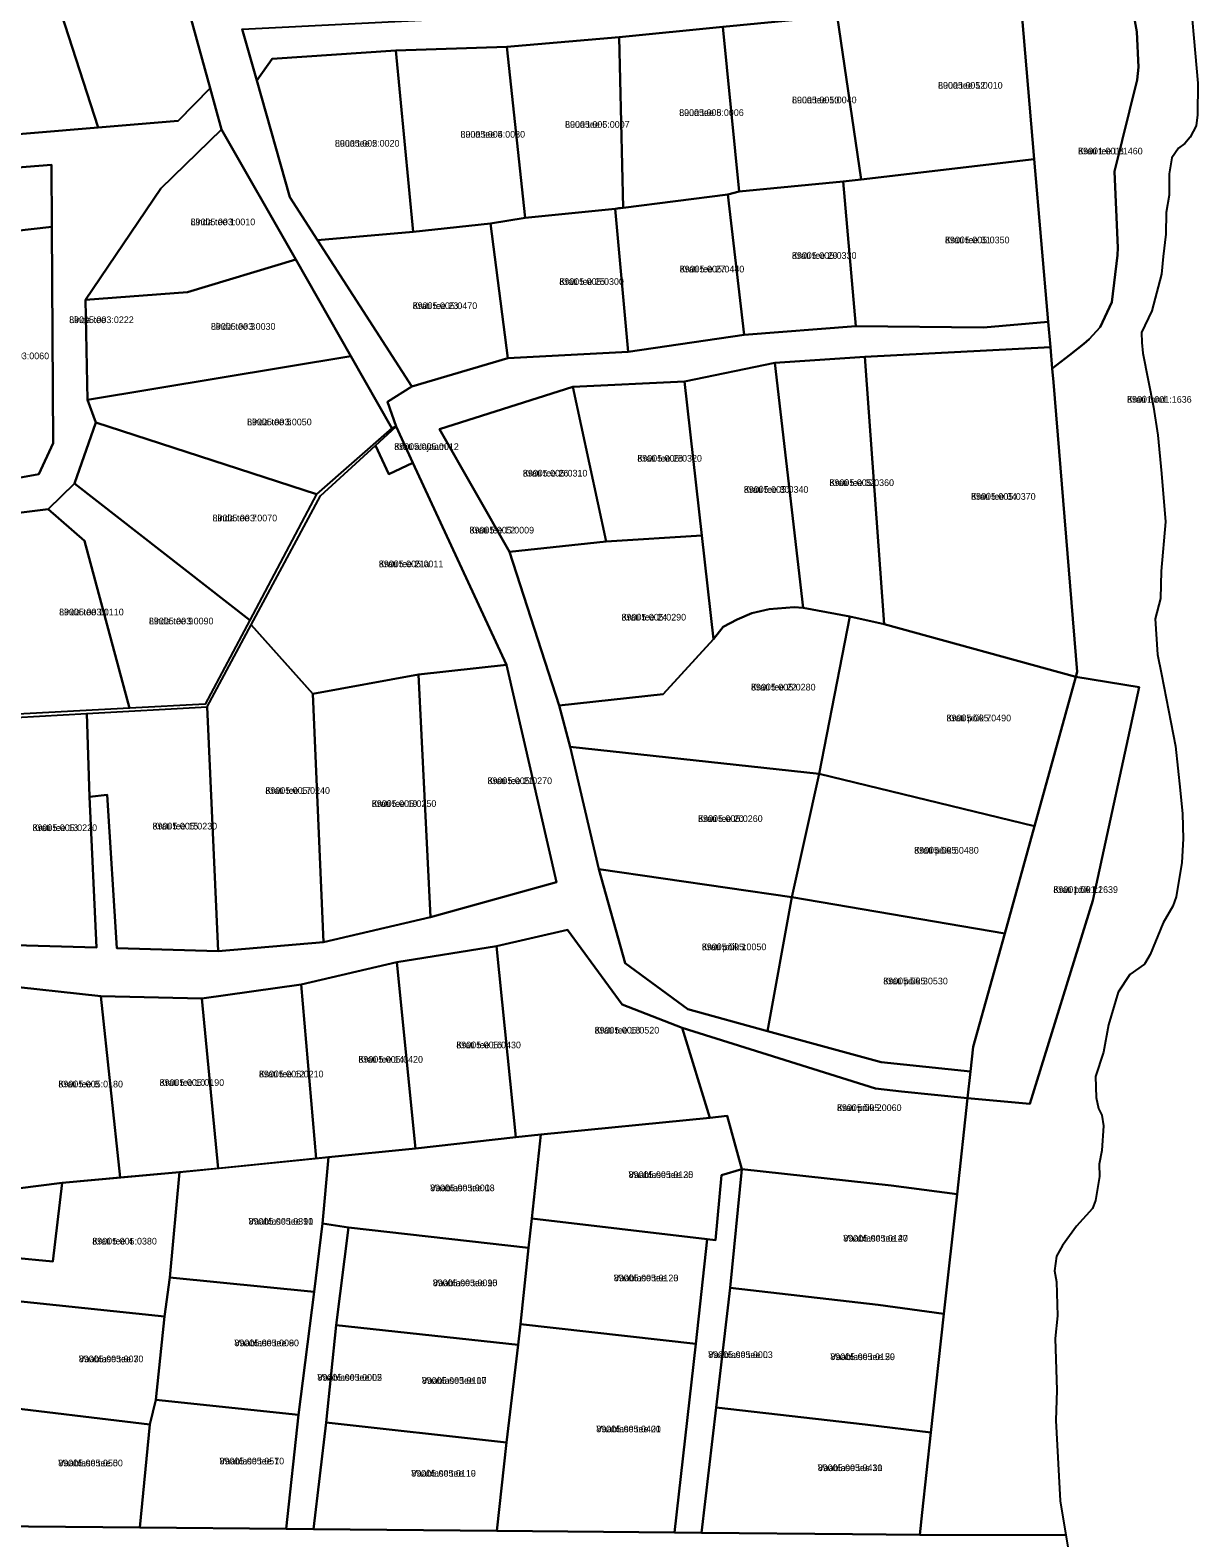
# Model space of a CAD drawing. Extents: x 526849 to 562296, y 6591741 to 6618546.
# Drawn here: x 551396.1 to 551658.3, y 6597667.2 to 6598005.8 of the extents above; entities that cross this region are included whole.
import ezdxf

# ---------------------------------------------------------------- set-up
doc = ezdxf.new("R2010")
doc.units = 0
for name, color, linetype in [('L_AADRESS', 7, 'Continuous'), ('PIIR', 7, 'Continuous'), ('TUNNUS', 7, 'Continuous')]:
    doc.layers.add(name, color=color, linetype=linetype)

msp = doc.modelspace()

# ---------------------------------------------------------------- linework, layer by layer
at = {"layer": 'PIIR'}
for points in [[(551396.53, 6598030.06), (551411.39, 6597983.93), (551381.8, 6597981.48), (551379.03, 6597991.79), (551380.47, 6597994.09), (551368.86, 6598029.7), (551393.92, 6598038.16)], [(551436.53, 6597992.77), (551429.32, 6597985.42), (551411.39, 6597983.93), (551396.53, 6598030.06), (551424.12, 6598037.92)], [(551617.86, 6598020.09), (551641.46, 6598022.51), (551644.15, 6598007.88), (551644.59, 6598005.37), (551644.95, 6597997.5), (551644.67, 6597994.64), (551639.56, 6597974.03), (551640.3, 6597956.86), (551640.24, 6597955.25), (551638.99, 6597944.7), (551636.37, 6597939.05), (551633.87, 6597936.37), (551632.7, 6597935.3), (551629.48, 6597932.79), (551625.6, 6597929.78), (551625.19, 6597934.56), (551624.69, 6597940.3), (551621.56, 6597976.84), (551618.46, 6598013.03)], [(551485.5, 6598008.09), (551511.34, 6598009.59), (551536.84, 6598012.08), (551561.17, 6598014.48), (551602.38, 6598018.5), (551617.86, 6598020.09), (551618.46, 6598013.03), (551577.33, 6598009.02), (551551.65, 6598006.5), (551528.39, 6598004.23), (551503.17, 6598002.03), (551478.25, 6598001.21), (551450.49, 6597999.32), (551446.99, 6597994.51), (551443.72, 6598005.99), (551446.75, 6598006.13)], [(551618.46, 6598013.03), (551621.56, 6597976.84), (551582.72, 6597972.25), (551577.33, 6598009.02)], [(551551.65, 6598006.5), (551577.33, 6598009.02), (551582.72, 6597972.25), (551578.64, 6597971.77), (551555.29, 6597969.57)], [(551551.65, 6598006.5), (551555.29, 6597969.57), (551552.79, 6597968.88), (551529.27, 6597965.9), (551528.39, 6598004.23)], [(551478.25, 6598001.21), (551503.17, 6598002.03), (551507.23, 6597963.65), (551499.49, 6597962.33), (551482.12, 6597960.5)], [(551528.39, 6598004.23), (551529.27, 6597965.9), (551528.2, 6597965.77), (551527.5, 6597965.68), (551507.23, 6597963.65), (551503.17, 6598002.03)], [(551454.45, 6597968.27), (551446.99, 6597994.51), (551450.49, 6597999.32), (551478.25, 6598001.21), (551482.12, 6597960.5), (551460.64, 6597958.65)], [(551455.76, 6597954.25), (551431.42, 6597946.97), (551408.54, 6597945.23), (551425.48, 6597970.24), (551439.08, 6597983.5)], [(551400.88, 6597975.53), (551400.97, 6597961.61), (551370.45, 6597958.16), (551379.6, 6597902.72), (551355.98, 6597898.45), (551352.67, 6597971.71)], [(551578.64, 6597971.77), (551582.72, 6597972.25), (551621.56, 6597976.84), (551624.69, 6597940.3), (551610.16, 6597938.99), (551581.52, 6597939.28)], [(551555.29, 6597969.57), (551578.64, 6597971.77), (551581.52, 6597939.28), (551556.43, 6597937.32), (551552.79, 6597968.88)], [(551527.5, 6597965.68), (551529.27, 6597965.9), (551552.79, 6597968.88), (551556.43, 6597937.32), (551530.36, 6597933.55)], [(551499.49, 6597962.33), (551507.23, 6597963.65), (551527.5, 6597965.68), (551530.36, 6597933.55), (551503.35, 6597932.1)], [(551401.3, 6597913.03), (551398.09, 6597906.05), (551379.6, 6597902.72), (551370.45, 6597958.16), (551400.97, 6597961.61)], [(551503.35, 6597932.1), (551481.82, 6597925.73), (551460.64, 6597958.65), (551482.12, 6597960.5), (551499.49, 6597962.33)], [(551468.14, 6597932.53), (551409, 6597922.74), (551408.54, 6597945.23), (551431.42, 6597946.97), (551455.76, 6597954.25)], [(551625.86, 6597926.71), (551631.24, 6597861.68), (551630.92, 6597860.53), (551587.85, 6597872.35), (551583.52, 6597932.38), (551625.19, 6597934.56), (551625.6, 6597929.78)], [(551468.14, 6597932.53), (551477.35, 6597916.37), (551460.43, 6597901.54), (551410.86, 6597917.63), (551409, 6597922.74)], [(551567.67, 6597876.17), (551562.07, 6597875.78), (551558.19, 6597874.87), (551554.84, 6597873.44), (551551.71, 6597871.74), (551549.56, 6597868.99), (551546.92, 6597892.26), (551543.01, 6597926.86), (551563.31, 6597931.09), (551569.72, 6597876.03)], [(551580.19, 6597874.07), (551569.72, 6597876.03), (551563.31, 6597931.09), (551583.52, 6597932.38), (551587.85, 6597872.35)], [(551517.98, 6597925.66), (551525.46, 6597890.96), (551503.71, 6597888.65), (551488.02, 6597916.15)], [(551517.98, 6597925.66), (551543.01, 6597926.86), (551546.92, 6597892.26), (551525.46, 6597890.96)], [(551445.43, 6597873.28), (551406.04, 6597903.96), (551410.86, 6597917.63), (551460.43, 6597901.54)], [(551473.65, 6597912.51), (551478.29, 6597916.76), (551482.07, 6597908.59), (551476.62, 6597906.07)], [(551445.76, 6597872.2), (551461.32, 6597901.21), (551473.65, 6597912.51), (551476.62, 6597906.07), (551482.07, 6597908.59), (551503.05, 6597863.22), (551483.31, 6597861.09), (551459.62, 6597856.74)], [(551445.43, 6597873.28), (551435.43, 6597854.42), (551418.39, 6597853.49), (551408.35, 6597891.08), (551400.15, 6597898.22), (551406.04, 6597903.96)], [(551408.35, 6597891.08), (551418.39, 6597853.49), (551389.06, 6597851.9), (551386.85, 6597896.53), (551400.15, 6597898.22)], [(551538.23, 6597856.64), (551514.87, 6597854.11), (551503.71, 6597888.65), (551525.46, 6597890.96), (551546.92, 6597892.26), (551549.56, 6597868.99)], [(551573.28, 6597838.78), (551517.39, 6597844.86), (551514.87, 6597854.11), (551538.23, 6597856.64), (551549.56, 6597868.99), (551551.71, 6597871.74), (551554.84, 6597873.44), (551558.19, 6597874.87), (551562.07, 6597875.78), (551567.67, 6597876.17), (551569.72, 6597876.03), (551580.19, 6597874.07)], [(551580.19, 6597874.07), (551587.85, 6597872.35), (551630.92, 6597860.53), (551621.62, 6597827.01), (551573.28, 6597838.78)], [(551459.62, 6597856.74), (551461.95, 6597800.95), (551438.35, 6597798.94), (551435.9, 6597853.83), (551445.76, 6597872.2)], [(551483.31, 6597861.09), (551503.05, 6597863.22), (551514.3, 6597814.46), (551486.03, 6597806.56)], [(551483.31, 6597861.09), (551486.03, 6597806.56), (551461.95, 6597800.95), (551459.62, 6597856.74)], [(551630.92, 6597860.53), (551645.12, 6597858.26), (551634.73, 6597810.31), (551620.57, 6597764.67), (551606.61, 6597765.95), (551607.27, 6597771.91), (551607.88, 6597777.48), (551614.93, 6597802.89), (551621.62, 6597827.01)], [(551438.35, 6597798.94), (551415.57, 6597799.6), (551413.44, 6597834.03), (551409.48, 6597833.56), (551408.85, 6597852.33), (551435.9, 6597853.83)], [(551409.48, 6597833.56), (551411.05, 6597799.73), (551384.73, 6597800.49), (551382.23, 6597850.85), (551408.85, 6597852.33)], [(551517.39, 6597844.86), (551573.28, 6597838.78), (551567.11, 6597811.04), (551523.78, 6597817.35)], [(551573.28, 6597838.78), (551621.62, 6597827.01), (551614.93, 6597802.89), (551567.11, 6597811.04)], [(551567.11, 6597811.04), (551561.65, 6597780.95), (551543.77, 6597785.94), (551529.71, 6597796.25), (551523.78, 6597817.35)], [(551567.11, 6597811.04), (551614.93, 6597802.89), (551607.88, 6597777.48), (551607.27, 6597771.91), (551587.17, 6597773.97), (551561.65, 6597780.95)], [(551505.18, 6597757.16), (551500.84, 6597800.03), (551516.8, 6597803.7), (551529.03, 6597786.94), (551542.51, 6597781.71), (551548.73, 6597761.5), (551510.79, 6597757.76)], [(551478.44, 6597796.45), (551500.84, 6597800.03), (551505.18, 6597757.16), (551482.64, 6597754.63)], [(551482.64, 6597754.63), (551463.12, 6597752.63), (551460.33, 6597752.35), (551457, 6597791.45), (551478.44, 6597796.45)], [(551412.02, 6597788.8), (551416.31, 6597748.08), (551403.3, 6597746.92), (551393.27, 6597745.66), (551388.62, 6597791.38)], [(551434.66, 6597788.28), (551438.33, 6597750.14), (551429.66, 6597749.27), (551416.31, 6597748.08), (551412.02, 6597788.8)], [(551460.33, 6597752.35), (551438.33, 6597750.14), (551434.66, 6597788.28), (551457, 6597791.45)], [(551604.24, 6597744.33), (551589.43, 6597746.32), (551555.89, 6597749.95), (551552.61, 6597761.96), (551548.73, 6597761.5), (551542.51, 6597781.71), (551585.92, 6597768.07), (551591.74, 6597767.41), (551606.61, 6597765.95)], [(551510.79, 6597757.76), (551548.73, 6597761.5), (551552.61, 6597761.96), (551555.89, 6597749.95), (551551.32, 6597748.66), (551550.03, 6597733.99), (551548.12, 6597734.22), (551508.74, 6597738.87)], [(551482.64, 6597754.63), (551505.18, 6597757.16), (551510.79, 6597757.76), (551508.74, 6597738.87), (551508.02, 6597732.27), (551467.62, 6597736.88), (551461.76, 6597737.76), (551463.12, 6597752.63)], [(551429.66, 6597749.27), (551463.12, 6597752.63), (551461.76, 6597737.76), (551459.91, 6597722.4), (551427.5, 6597725.62)], [(551391.89, 6597730.11), (551401.24, 6597729.25), (551403.3, 6597746.92), (551429.66, 6597749.27), (551427.5, 6597725.62), (551426.26, 6597716.88), (551390.49, 6597720.63)], [(551545.56, 6597710.72), (551548.12, 6597734.22), (551550.03, 6597733.99), (551551.32, 6597748.66), (551555.89, 6597749.95), (551553.3, 6597723.34), (551550.18, 6597696.45), (551546.88, 6597668.32), (551540.83, 6597668.38)], [(551586.56, 6597719.5), (551553.3, 6597723.34), (551555.89, 6597749.95), (551589.43, 6597746.32), (551604.24, 6597744.33), (551601.29, 6597717.46)], [(551456.4, 6597694.78), (551459.91, 6597722.4), (551461.76, 6597737.76), (551467.62, 6597736.88), (551464.84, 6597714.96), (551462.57, 6597693.1), (551459.72, 6597669.11), (551453.61, 6597669.17)], [(551506.18, 6597715.13), (551508.02, 6597732.27), (551508.74, 6597738.87), (551548.12, 6597734.22), (551545.56, 6597710.72)], [(551508.02, 6597732.27), (551506.18, 6597715.13), (551505.67, 6597710.5), (551464.84, 6597714.96), (551467.62, 6597736.88)], [(551459.91, 6597722.4), (551456.4, 6597694.78), (551424.34, 6597698.14), (551426.26, 6597716.88), (551427.5, 6597725.62)], [(551586.56, 6597719.5), (551601.29, 6597717.46), (551598.37, 6597690.84), (551583.61, 6597692.66), (551550.18, 6597696.45), (551553.3, 6597723.34)], [(551379.78, 6597697.5), (551381.69, 6597704.62), (551382.36, 6597705.74), (551388.61, 6597704.2), (551390.49, 6597720.63), (551426.26, 6597716.88), (551424.34, 6597698.14), (551422.96, 6597692.59), (551386.74, 6597696.97)], [(551505.67, 6597710.5), (551503.11, 6597688.56), (551462.57, 6597693.1), (551464.84, 6597714.96)], [(551500.9, 6597668.74), (551503.11, 6597688.56), (551505.67, 6597710.5), (551506.18, 6597715.13), (551545.56, 6597710.72), (551540.83, 6597668.38)], [(551420.73, 6597669.47), (551422.96, 6597692.59), (551424.34, 6597698.14), (551456.4, 6597694.78), (551453.61, 6597669.17)], [(551422.96, 6597692.59), (551420.73, 6597669.47), (551378.96, 6597669.85), (551386.74, 6597696.97)], [(551550.18, 6597696.45), (551583.61, 6597692.66), (551598.37, 6597690.84), (551596.39, 6597672.83), (551595.85, 6597667.87), (551580.76, 6597668.01), (551546.88, 6597668.32)], [(551503.11, 6597688.56), (551500.9, 6597668.74), (551459.72, 6597669.11), (551462.57, 6597693.1)]]:
    msp.add_lwpolyline(points, close=True, dxfattribs=at)
for points in [[(551443.72, 6598005.99), (551446.99, 6597994.51), (551454.45, 6597968.27), (551460.64, 6597958.65), (551481.82, 6597925.73), (551476.38, 6597922.28), (551478.29, 6597916.76), (551477.35, 6597916.37), (551468.14, 6597932.53), (551455.76, 6597954.25), (551439.08, 6597983.5), (551436.53, 6597992.77), (551424.12, 6598037.92)], [(551656.16, 6598018.34), (551658.3, 6597993.9), (551658.22, 6597986.75), (551657.91, 6597984.29), (551656.56, 6597981.75), (551655.37, 6597980.32), (551653.94, 6597979.29), (551652.44, 6597977.13), (551651.88, 6597973.5), (551651.88, 6597968.73), (551651.16, 6597964.85), (551651.08, 6597960), (551650.5, 6597954.98), (551650.11, 6597950.95), (551647.95, 6597942.75), (551645.68, 6597937.86), (551645.76, 6597935.64), (551645.92, 6597933.25), (551648.38, 6597921.11), (551649.33, 6597914.84), (551650.14, 6597906.22), (551651.01, 6597895.35), (551650.06, 6597884.3), (551649.89, 6597878.17), (551648.7, 6597873.56), (551649.23, 6597865.58), (551650.11, 6597861.12), (551653.31, 6597844.94), (551654.35, 6597835.12), (551654.89, 6597829.75), (551654.97, 6597824.19), (551654.73, 6597818.87), (551653.46, 6597811.1), (551652.67, 6597809.03), (551650.53, 6597805.3), (551647.59, 6597798.16), (551646.32, 6597796.01), (551643.06, 6597793.71), (551640.44, 6597789.74), (551638.22, 6597782.36), (551637.11, 6597776.25), (551635.29, 6597770.77), (551635.44, 6597766.09), (551636, 6597763.63), (551636.71, 6597762.12), (551637.11, 6597759.74), (551636.71, 6597754.18), (551636.16, 6597751.09), (551636.24, 6597748.31), (551635.29, 6597742.91), (551634.65, 6597741.17), (551631.08, 6597737.2), (551627.92, 6597732.8), (551626.58, 6597730.46), (551626.11, 6597727.13), (551626.55, 6597724.66), (551626.79, 6597717.04), (551626.24, 6597711.96), (551626.61, 6597700.3), (551626.41, 6597693.56), (551627.37, 6597675.51), (551628.68, 6597667.76), (551595.85, 6597667.87), (551596.39, 6597672.83), (551598.37, 6597690.84), (551601.29, 6597717.46), (551604.24, 6597744.33), (551606.61, 6597765.95), (551620.57, 6597764.67), (551634.73, 6597810.31), (551645.12, 6597858.26), (551630.92, 6597860.53), (551631.24, 6597861.68), (551625.86, 6597926.71), (551625.6, 6597929.78), (551629.48, 6597932.79), (551632.7, 6597935.3), (551633.87, 6597936.37), (551636.37, 6597939.05), (551638.99, 6597944.7), (551640.24, 6597955.25), (551640.3, 6597956.86), (551639.56, 6597974.03), (551644.67, 6597994.64), (551644.95, 6597997.5), (551644.59, 6598005.37), (551644.15, 6598007.88)], [(551381.8, 6597981.48), (551411.39, 6597983.93), (551429.32, 6597985.42), (551436.53, 6597992.77), (551439.08, 6597983.5), (551425.48, 6597970.24), (551408.54, 6597945.23), (551409, 6597922.74), (551410.86, 6597917.63), (551406.04, 6597903.96), (551400.15, 6597898.22), (551386.85, 6597896.53)], [(551379.6, 6597902.72), (551398.09, 6597906.05), (551401.3, 6597913.03), (551400.97, 6597961.61), (551400.88, 6597975.53), (551352.67, 6597971.71)], [(551384.73, 6597800.49), (551411.05, 6597799.73), (551409.48, 6597833.56), (551413.44, 6597834.03), (551415.57, 6597799.6), (551438.35, 6597798.94), (551461.95, 6597800.95), (551486.03, 6597806.56), (551514.3, 6597814.46), (551503.05, 6597863.22), (551482.07, 6597908.59), (551478.29, 6597916.76), (551476.38, 6597922.28), (551481.82, 6597925.73), (551503.35, 6597932.1), (551530.36, 6597933.55), (551556.43, 6597937.32), (551581.52, 6597939.28), (551610.16, 6597938.99), (551624.69, 6597940.3), (551625.19, 6597934.56), (551583.52, 6597932.38), (551563.31, 6597931.09), (551543.01, 6597926.86), (551517.98, 6597925.66), (551488.02, 6597916.15), (551503.71, 6597888.65), (551514.87, 6597854.11), (551517.39, 6597844.86), (551523.78, 6597817.35), (551529.71, 6597796.25), (551543.77, 6597785.94), (551561.65, 6597780.95), (551587.17, 6597773.97), (551607.27, 6597771.91), (551606.61, 6597765.95), (551591.74, 6597767.41), (551585.92, 6597768.07), (551542.51, 6597781.71), (551529.03, 6597786.94), (551516.8, 6597803.7), (551500.84, 6597800.03), (551478.44, 6597796.45), (551457, 6597791.45), (551434.66, 6597788.28), (551412.02, 6597788.8), (551388.62, 6597791.38)], [(551393.27, 6597745.66), (551403.3, 6597746.92), (551401.24, 6597729.25), (551391.89, 6597730.11)], [(551357.16, 6597664.73), (551357.49, 6597672.95), (551372.45, 6597669.91), (551378.96, 6597669.85), (551420.73, 6597669.47), (551453.61, 6597669.17), (551459.72, 6597669.11), (551500.9, 6597668.74), (551540.83, 6597668.38), (551546.88, 6597668.32), (551580.76, 6597668.01), (551595.85, 6597667.87), (551628.68, 6597667.76), (551631.08, 6597653.46)]]:
    msp.add_lwpolyline(points, dxfattribs=at)

# ---------------------------------------------------------------- texts
at = {"layer": 'L_AADRESS'}
for s, p in [('Luua tee 12', (551599.97, 6597992.64)), ('Luua tee 10', (551567.18, 6597989.36)), ('Luua tee 6', (551516.22, 6597983.86)), ('Luua tee 8', (551541.84, 6597986.52)), ('Luua tee 4', (551492.74, 6597981.65)), ('Luua tee 2', (551464.55, 6597979.63)), ('Krati tee L3', (551631.41, 6597977.88)), ('Linda tee 1', (551432.15, 6597961.97)), ('Krati tee 31', (551601.52, 6597957.91)), ('Krati tee 29', (551567.16, 6597954.42)), ('Krati tee 27', (551541.96, 6597951.37)), ('Krati tee 25', (551514.93, 6597948.57)), ('Krati tee 23', (551482, 6597943.14)), ('Linda tee', (551404.88, 6597939.99)), ('Linda tee 3', (551436.71, 6597938.49)), ('Krati rand', (551642.41, 6597922.1)), ('Linda tee 5', (551444.83, 6597917.04)), ('Krati alajaam', (551477.86, 6597911.5)), ('Krati tee 28', (551532.45, 6597908.87)), ('Krati tee 26', (551506.74, 6597905.53)), ('Krati tee 32', (551575.58, 6597903.4)), ('Krati tee 30', (551556.36, 6597901.87)), ('Krati tee 34', (551607.38, 6597900.31)), ('Linda tee 7', (551437.08, 6597895.46)), ('Krati tee L2', (551494.76, 6597892.74)), ('Krati tee 21a', (551474.4, 6597885.16)), ('Linda tee 11', (551402.62, 6597874.35)), ('Linda tee 9', (551422.79, 6597872.32)), ('Krati tee 24', (551528.9, 6597873.19)), ('Krati tee 22', (551557.97, 6597857.48)), ('Krati põik 7', (551601.87, 6597850.54)), ('Krati tee 21', (551498.8, 6597836.45)), ('Krati tee 17', (551448.93, 6597834.26)), ('Krati tee 19', (551472.82, 6597831.32)), ('Krati tee 20', (551546.09, 6597827.95)), ('Krati tee 13', (551396.64, 6597825.9)), ('Krati tee 15', (551423.6, 6597826.26)), ('Krati põik 5', (551594.6, 6597820.84)), ('Krati põik L2', (551625.86, 6597812.02)), ('Krati põik 1', (551546.92, 6597799.15)), ('Krati põik 3', (551587.66, 6597791.48)), ('Krati tee 18', (551522.86, 6597780.43)), ('Krati tee 16', (551491.81, 6597777.12)), ('Krati tee 14', (551469.82, 6597773.88)), ('Krati tee 12', (551447.49, 6597770.58)), ('Krati tee 8', (551402.46, 6597768.33)), ('Krati tee 10', (551425.18, 6597768.68)), ('Krati põik 2', (551577.28, 6597763.02)), ('Vaablase tee 25', (551530.49, 6597747.98)), ('Vaablase tee 13', (551485.92, 6597745.02)), ('Vaablase tee 11', (551445.16, 6597737.51)), ('Krati tee 4', (551410.07, 6597733.05)), ('Vaablase tee 27', (551578.69, 6597733.71)), ('Vaablase tee 15', (551486.52, 6597723.69)), ('Vaablase tee 23', (551527.16, 6597724.79)), ('Vaablase tee 9', (551441.97, 6597710.2)), ('Vaablase tee 3', (551407.05, 6597706.61)), ('Vaablase tee L3', (551548.36, 6597707.56)), ('Vaablase tee 29', (551575.78, 6597707.09)), ('Vaablase tee L2', (551460.61, 6597702.45)), ('Vaablase tee 17', (551484.06, 6597701.76)), ('Vaablase tee 21', (551523.23, 6597690.88)), ('Vaablase tee 5', (551402.43, 6597683.22)), ('Vaablase tee 7', (551438.64, 6597683.66)), ('Vaablase tee 31', (551572.96, 6597682.16)), ('Vaablase tee 19', (551481.69, 6597680.92))]:
    msp.add_text(s, height=1.5, dxfattribs=at).set_placement(p)
at = {"layer": 'TUNNUS'}
for s, p in [('89005:005:0010', (551599.97, 6597992.64)), ('89005:005:0040', (551567.18, 6597989.36)), ('89005:005:0007', (551516.22, 6597983.86)), ('89005:005:0006', (551541.84, 6597986.52)), ('89005:005:0030', (551492.74, 6597981.65)), ('89005:005:0020', (551464.55, 6597979.63)), ('89001:001:1460', (551631.41, 6597977.88)), ('89005:003:0010', (551432.15, 6597961.97)), ('89005:005:0350', (551601.52, 6597957.91)), ('89005:005:0330', (551567.16, 6597954.42)), ('89005:005:0440', (551541.96, 6597951.37)), ('89005:005:0300', (551514.93, 6597948.57)), ('89005:005:0470', (551482, 6597943.14)), ('89005:003:0222', (551404.88, 6597939.99)), ('89005:003:0030', (551436.71, 6597938.49)), ('89005:003:0060', (551385.88, 6597931.88)), ('89001:001:1636', (551642.41, 6597922.1)), ('89005:003:0050', (551444.83, 6597917.04)), ('89005:005:0012', (551477.86, 6597911.5)), ('89005:005:0320', (551532.45, 6597908.87)), ('89005:005:0310', (551506.74, 6597905.53)), ('89005:005:0360', (551575.58, 6597903.4)), ('89005:005:0340', (551556.36, 6597901.87)), ('89005:005:0370', (551607.38, 6597900.31)), ('89005:003:0070', (551437.08, 6597895.46)), ('89005:005:0009', (551494.76, 6597892.74)), ('89005:005:0011', (551474.4, 6597885.16)), ('89005:003:0110', (551402.62, 6597874.35)), ('89005:003:0090', (551422.79, 6597872.32)), ('89005:005:0290', (551528.9, 6597873.19)), ('89005:005:0280', (551557.97, 6597857.48)), ('89005:005:0490', (551601.87, 6597850.54)), ('89005:005:0270', (551498.8, 6597836.45)), ('89005:005:0240', (551448.93, 6597834.26)), ('89005:005:0250', (551472.82, 6597831.32)), ('89005:005:0260', (551546.09, 6597827.95)), ('89005:005:0220', (551396.64, 6597825.9)), ('89005:005:0230', (551423.6, 6597826.26)), ('89005:005:0480', (551594.6, 6597820.84)), ('89001:001:1639', (551625.86, 6597812.02)), ('89005:005:0050', (551546.92, 6597799.15)), ('89005:005:0530', (551587.66, 6597791.48)), ('89005:005:0520', (551522.86, 6597780.43)), ('89005:005:0430', (551491.81, 6597777.12)), ('89005:005:0420', (551469.82, 6597773.88)), ('89005:005:0210', (551447.49, 6597770.58)), ('89005:005:0180', (551402.46, 6597768.33)), ('89005:005:0190', (551425.18, 6597768.68)), ('89005:005:0060', (551577.28, 6597763.02)), ('89005:005:0130', (551530.49, 6597747.98)), ('89005:005:0008', (551485.92, 6597745.02)), ('89005:005:0390', (551445.16, 6597737.51)), ('89005:005:0380', (551410.07, 6597733.05)), ('89005:005:0140', (551578.69, 6597733.71)), ('89005:005:0090', (551486.52, 6597723.69)), ('89005:005:0120', (551527.16, 6597724.79)), ('89005:005:0080', (551441.97, 6597710.2)), ('89005:005:0070', (551407.05, 6597706.61)), ('89005:005:0003', (551548.36, 6597707.56)), ('89005:005:0150', (551575.78, 6597707.09)), ('89005:005:0005', (551460.61, 6597702.45)), ('89005:005:0100', (551484.06, 6597701.76)), ('89005:005:0400', (551523.23, 6597690.88)), ('89005:005:0500', (551402.43, 6597683.22)), ('89005:005:0510', (551438.64, 6597683.66)), ('89005:005:0410', (551572.96, 6597682.16)), ('89005:005:0110', (551481.69, 6597680.92))]:
    msp.add_text(s, height=1.5, dxfattribs=at).set_placement(p)

doc.saveas('drawing.dxf')
